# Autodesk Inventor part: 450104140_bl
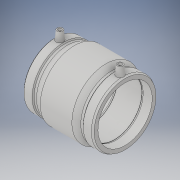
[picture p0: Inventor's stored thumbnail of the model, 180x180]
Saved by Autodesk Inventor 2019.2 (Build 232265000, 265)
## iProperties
Created: 2017-06
Part Number: 450104140_bl
Material: Generic
Description: PLASSON COUPLER 140 PN25
Document SubType Name: Modeling
Designer: KIM
Mass: 8622.19 g
Surface Area: 6772.47 cm^2
Volume: 8622.19 cm^3
Density: 1 g/cm^3
Appearance: Default
Author: KIM
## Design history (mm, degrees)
derived "450104.ipt"
feature "Solid1::450104.ipt" dims "ScaleForDerivedMember" = 10
tag "TaggingFeature1"
body "Solid1"
other parameters: "d0" = 181 [user parameter], "d2" = 175 [user parameter], "d3" = 89 [user parameter], "d4" = 45.25 [user parameter], "d5" = 157.5 [user parameter], "d6" = 112 [user parameter], "d8" = 168 deg [user parameter], "d10" = 35.6 [user parameter], "d11" = 11.86667 [user parameter], "d13" = 181 [user parameter], "d14" = 17.6296 [user parameter], "d15" = 89 [user parameter], "d16" = 89 [user parameter], "d17" = 138.6 [user parameter], "d19" = 3.52592 [user parameter], "d20" = 168 deg [user parameter], "d22" = 164.5 [user parameter], "d23" = 175 [user parameter], "d24" = 159.565 [user parameter], "d25" = 135 deg [user parameter], "d26" = 81.45 [user parameter], "d27" = 135 deg [user parameter], "d29" = 105 [user parameter], "d30" = 15 [user parameter], "d31" = 63.35 [user parameter], "d34" = 5 deg [user parameter], "d35" = 15 [user parameter], "d39" = 5 deg [user parameter], "d41" = 4 [user parameter], "d42" = 14 [user parameter], "d43" = 0 [user parameter], "d45" = 4 [user parameter], "d46" = 14 [user parameter], "d47" = 0 [user parameter], "d48" = 3 [user parameter], "d49" = 0 [user parameter], "d50" = 3 [user parameter], "d51" = 0 [user parameter], "d52" = 25.81 [user parameter], "d53" = 6.4525 [user parameter], "L_" = 181 [user parameter], "L_1" = 89 [user parameter], "D_" = 175 [user parameter], "A_" = 105 [user parameter], "d_2" = 12 [user parameter]
